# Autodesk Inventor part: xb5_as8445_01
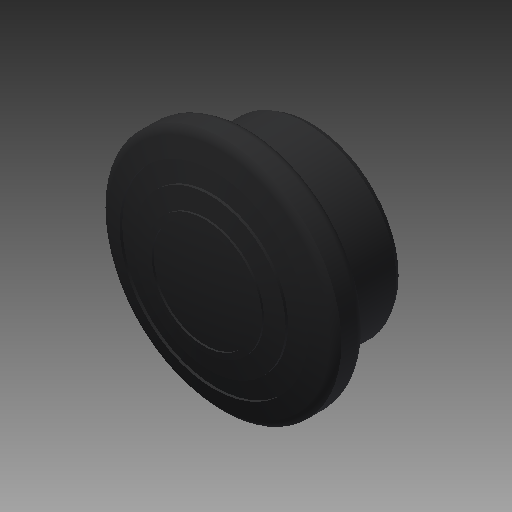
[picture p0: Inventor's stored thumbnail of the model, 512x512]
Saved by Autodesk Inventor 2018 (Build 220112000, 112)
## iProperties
Company: TraceParts S.A.
Created: 2018-04
Part Number: xb5_as8445_01
Checked By: TraceParts S.A.
Material: Goma
Catalog Web Link: www.traceparts.com
Document SubType Name: Modeling
Designer: TraceParts
Density: 0.93 g/cm^3
Appearance: Goma - Negro
Author: TraceParts
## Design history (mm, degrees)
feature "xb5_as8445_01.ipt"
body "Solid1"
